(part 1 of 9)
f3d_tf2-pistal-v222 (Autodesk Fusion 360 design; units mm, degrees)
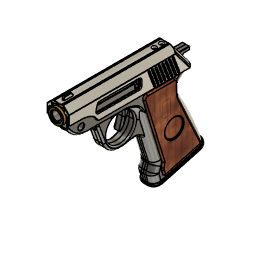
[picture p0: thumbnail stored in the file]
description: Part Number
part number: Dante
part number: catch_housing_front
part number: catch_housing_rear
part number: catch
part number: slide
part number: barrel
part number: priming_handle
part number: front_sight
part number: turnaround
part number: pusher
part number: plunger_tube
part number: plunger_rod
part number: plunger_head
part number: plunger_rod_guide
part number: frame_rear
part number: frame_front
part number: frame
part number: trigger_spring_cover
part number: mag_detent
base_feature "Base Feature1"
base_feature "Base Feature1"
base_feature "Base Feature1"
base_feature "Base Feature1"
base_feature "Base Feature1"
base_feature "Base Feature1"
base_feature "Base Feature1"
base_feature "Base Feature1"
base_feature "Base Feature1"
base_feature "Base Feature1"
base_feature "Base Feature1"
base_feature "Base Feature1"
base_feature "Base Feature1"
base_feature "Base Feature1"
base_feature "Base Feature1"
base_feature "Base Feature1"
base_feature "Base Feature1"
base_feature "Base Feature1"
base_feature "Base Feature1"
base_feature "Base Feature1"
base_feature "Base Feature1"
base_feature "Base Feature1"
base_feature "Base Feature1"
base_feature "Base Feature1"
canvas "Canvas1"
sketch "Sketch1" plane through (-12.5019, 0, 0) normal (-1, 0, 0) x axis (0, -1, 0)
  line L1 (-219.2201, -134.5487) -> (-199.7373, -62.1263)
  line L2 (-219.23, -134.546) -> (-219.2201, -134.5487)
  line L3 (-219.2307, -134.5487) -> (-219.23, -134.546)
  line L4 (-203.3742, -138.8144) -> (-219.2307, -134.5487)
  line L5 (-183.8907, -66.3893) -> (-203.3742, -138.8144)
  line L6 (-199.7373, -62.1263) -> (-183.8907, -66.3893)
  line L7 (-226.3299, -153.1631) -> (-159.8398, -35.3102)
  line L8 (-112.2983, -161.9989) -> (-159.8398, -35.3102)
  line L9 (-112.2983, -161.9989) -> (-132.8986, -57.2662)
  line L10 (-159.8398, -35.3102) -> (-187.1527, -53.6803)
  line L11 (-226.3299, -153.1631) -> (-187.1527, -53.6803)
  circle C1 centre (-159.8398, -35.3102) radius 135.3153
  circle C2 centre (-159.8398, -35.3102) radius 34.7548
  arc A1 centre (-131.4034, -38.3747) radius 28.6011 clockwise from (-130.9894, -66.9728) to (-159.8398, -35.3102)
  arc A2 centre (-188.5512, -53.174) radius 1.4873 clockwise from (-189.9497, -52.6677) to (-187.1527, -53.6803)
  circle C3 centre (-159.8398, -35.3102) radius 14.267
  point P8 (-159.8398, -35.3102)
  point P9 (-159.8398, -35.3102)
  point P10 (-226.3299, -153.1631)
  point P11 (-112.2983, -161.9989)
  point P12 (-159.8398, -35.3102)
  point P13 (-189.9497, -52.6677)
  point P14 (-132.8986, -57.2662)
  point P15 (-130.9894, -66.9728)
  coincident P8 P9
  coincident C1 P10
  coincident C1 P11
  coincident P9 P12
  coincident C2 P13
  coincident C2 P14
  coincident L9 P15
  concentric C1 C3
  dimension "d1" angle L7 L8 = 50
extrude "Extrude1" new body sketch "Sketch1" profile of L4 L5 L6 C1 L7 L8 C2 L9 A1 L10 C3 L11 along normal blind 6.5 and against normal blind 31.5
fillet "Fillet1" radius 13.5
fillet "Fillet2" radius 7.5
shell "Shell1" innerThickness 5
fillet "Fillet3" radius 7
delete_face "DeleteFace1"
fillet "Fillet4" radius 9
sketch "Sketch2" plane through (-19.0019, 0, 0) normal (-1, 0, 0) x axis (0, -1, 0)
  line L1 (-140.4501, -65.5073) -> (-120.8998, -164.9015)
  line L2 (-151.3148, -58.0276) -> (-150.8034, -59.3904)
  line L3 (-187.1527, -53.6803) -> (-171.6782, -43.2725)
  line L4 (-226.3299, -153.1631) -> (-187.1527, -53.6803)
  line L5 (-207.1284, -169.7945) -> (-171.6782, -43.2725)
  line L6 (-171.6782, -43.2725) -> (-177.894, -39.8303)
  arc A1 centre (-131.4034, -38.3747) radius 28.6011 clockwise from (-140.4501, -65.5073) to (-150.8034, -59.3904)
  arc A2 centre (-138.6755, -53.2845) radius 13.5 clockwise from (-151.3148, -58.0276) to (-148.9653, -44.5456)
  arc A3 centre (-159.8398, -35.3102) radius 14.267 clockwise from (-171.6782, -43.2725) to (-148.9653, -44.5456)
  arc A4 centre (-159.8398, -35.3102) radius 135.3153 clockwise from (-120.8998, -164.9015) to (-226.3299, -153.1631)
  point P9 (-171.6782, -43.2725)
  point P13 (-171.6782, -43.2725)
  point P16 (-171.6782, -43.2725)
  coincident P9 P13
  coincident P9 P16
split "Split1"
move "Move1" TranslateX 0 TranslateY 2.5 TranslateZ 10
fillet "Fillet5" radius 20
move_face "MoveFace1" TranslateX 0 TranslateY 0 TranslateZ -10
delete_face "DeleteFace2"
fillet "Fillet6" radius 7.5
delete_face "DeleteFace3"
fillet "Fillet7" radius 17.5
fillet "Fillet8" radius 2
fillet "Fillet9" radius 2
fillet "Fillet10" radius 2
fillet "Fillet11" radius 2
sketch "Sketch1" plane through (0, 0, 0) normal (0, 0, 1) x axis (1, 0, 0)
  circle C1 centre (0, 0) radius 14.3492
  circle C2 centre (0, 0) radius 2.5
extrude "Extrude1" new body sketch "Sketch1" along normal blind 4
sketch "Sketch2" plane through (0, 0, 0) normal (0, 0, 1) x axis (1, 0, 0)
  curve K1 (20.9794, -0.931) -> (16.735, -2.4575)
  curve K2 (20.9794, 0.931) -> (16.735, 2.4575)
  line L1 (16.735, -2.4575) -> (14.1871, -2.0848)
  line L2 (16.735, 2.4575) -> (14.1871, 2.0848)
  line L3 (14.1871, 2.0848) -> (14.1871, -2.0848)
  arc A1 centre (0, 0) radius 21 clockwise from (20.9794, 0.931) to (20.9794, -0.931)
extrude "Extrude2" add sketch "Sketch2" along normal blind 4
fillet "Fillet1" radius 0.8
circular_pattern "C-Pattern1" countU 12 TotalAngle 360
sketch "Sketch3" plane through (0, 0, 0) normal (0, 0, 1) x axis (1, 0, 0)
  circle C1 centre (0, 0) radius 18
sketch "Sketch1" plane through (0, 0, 0) normal (0, 0, 1) x axis (1, 0, 0)
  circle C1 centre (0, 0) radius 16.1492
  circle C2 centre (0, 0) radius 2.5
extrude "Extrude1" new body sketch "Sketch1" along normal blind 4
sketch "Sketch2" plane through (0, 0, 0) normal (0, 0, 1) x axis (1, 0, 0)
  curve K1 (19.4926, -0.5366) -> (16.8599, -1.3577)
  curve K2 (19.4926, 0.5366) -> (16.8599, 1.3577)
  line L1 (16.8599, -1.3577) -> (16.0871, -1.2963)
  line L2 (16.8599, 1.3577) -> (16.0871, 1.2963)
  line L3 (16.0871, 1.2963) -> (16.0871, -1.2963)
  arc A1 centre (0, 0) radius 19.5 clockwise from (19.4926, 0.5366) to (19.4926, -0.5366)
extrude "Extrude2" add sketch "Sketch2" along normal blind 4
fillet "Fillet1" radius 0.8
circular_pattern "C-Pattern1" countU 24 TotalAngle 360
sketch "Sketch3" plane through (0, 0, 0) normal (0, 0, 1) x axis (1, 0, 0)
  circle C1 centre (0, 0) radius 18
sketch "Sketch1" plane through (0, 0, 0) normal (0, 0, 1) x axis (1, 0, 0)
  circle C1 centre (0, 0) radius 17.0492
  circle C2 centre (0, 0) radius 2.5
extrude "Extrude1" new body sketch "Sketch1" along normal blind 4
sketch "Sketch2" plane through (0, 0, 0) normal (0, 0, 1) x axis (1, 0, 0)
  curve K1 (18.7478, -0.2898) -> (16.8953, -0.8053)
  curve K2 (18.7478, 0.2898) -> (16.8953, 0.8053)
  line L1 (16.8953, -0.8053) -> (16.8953, 0.8053)
  arc A1 centre (0, 0) radius 18.75 clockwise from (18.7478, 0.2898) to (18.7478, -0.2898)
extrude "Extrude2" add sketch "Sketch2" along normal blind 4
fillet "Fillet1" radius 0.4
circular_pattern "C-Pattern1" countU 48 TotalAngle 360
sketch "Sketch3" plane through (0, 0, 0) normal (0, 0, 1) x axis (1, 0, 0)
  circle C1 centre (0, 0) radius 18
move "Move1"
position "Position1"
move "Move2"
sketch "Sketch1" plane through (0, 0, 0) normal (0, 0, 1) x axis (1, 0, 0)
  circle C1 centre (0, 0) radius 5.0492
  circle C2 centre (0, 0) radius 2.5
extrude "Extrude1" new body sketch "Sketch1" along normal blind 4
sketch "Sketch2" plane through (0, 0, 0) normal (0, 0, 1) x axis (1, 0, 0)
  curve K1 (6.7454, -0.2496) -> (5.6021, -0.6362)
  curve K2 (6.7454, 0.2496) -> (5.6021, 0.6362)
  line L1 (5.6021, -0.6362) -> (5.007, -0.5697)
  line L2 (5.6021, 0.6362) -> (5.007, 0.5697)
  line L3 (5.007, 0.5697) -> (5.007, -0.5697)
  arc A1 centre (0, 0) radius 6.75 clockwise from (6.7454, 0.2496) to (6.7454, -0.2496)
extrude "Extrude2" add sketch "Sketch2" along normal blind 4
fillet "Fillet1" radius 0.4
circular_pattern "C-Pattern1" countU 16 TotalAngle 360
sketch "Sketch3" plane through (0, 0, 0) normal (0, 0, 1) x axis (1, 0, 0)
  circle C1 centre (0, 0) radius 6
position "Position2"
move "Move1"
move "Move2" RotateAngle 55
move "Move3" TranslateX 0.3 TranslateY 0.5 TranslateZ 0
move "Move4"
sketch "Sketch3" plane through (13.9981, 0, 0) normal (-1, 0, 0) x axis (0, -1, 0)
  line L1 (-155.6873, -48.7302) -> (-149.7495, -64.5534)
  line L2 (-200.2987, -133.9094) -> (-171.9916, -32.8813)
  line L3 (-141.9595, -78.6785) -> (-127.1636, -153.9011)
  line L4 (-144.3334, -73.2936) -> (-142.3421, -78.6001)
  line L5 (-146.405, -67.7731) -> (-144.3334, -73.2936)
  curve K1 (-157.8654, -7.0015) -> (-158.666, -8.2069)
  curve K2 (-157.3054, -7.1515) -> (-157.2147, -8.5958)
  curve K3 (-157.2147, -8.5958) -> (-156.4821, -8.8445)
  curve K4 (-155.531, -7.7539) -> (-156.4821, -8.8445)
  curve K5 (-154.9954, -7.9757) -> (-155.094, -9.4194)
  curve K6 (-155.094, -9.4194) -> (-154.4002, -9.7616)
  curve K7 (-153.3148, -8.8045) -> (-154.4002, -9.7616)
  curve K8 (-152.8128, -9.0943) -> (-153.099, -10.5129)
  curve K9 (-153.099, -10.5129) -> (-152.4557, -10.9427)
  curve K10 (-151.2547, -10.1354) -> (-152.4557, -10.9427)
  curve K11 (-150.7948, -10.4883) -> (-151.2637, -11.8573)
  curve K12 (-151.2637, -11.8573) -> (-150.682, -12.3674)
  curve K13 (-149.3859, -11.7239) -> (-150.682, -12.3674)
  curve K14 (-148.9761, -12.1337) -> (-149.6196, -13.4298)
  curve K15 (-149.6196, -13.4298) -> (-149.1095, -14.0115)
  curve K16 (-147.7405, -13.5426) -> (-149.1095, -14.0115)
  curve K17 (-147.3876, -14.0025) -> (-148.1949, -15.2035)
  curve K18 (-148.1949, -15.2035) -> (-147.7651, -15.8468)
  curve K19 (-146.3466, -15.5606) -> (-147.7651, -15.8468)
  curve K20 (-146.0567, -16.0626) -> (-147.0138, -17.148)
  curve K21 (-147.0138, -17.148) -> (-146.6716, -17.8418)
  curve K22 (-145.2279, -17.7432) -> (-146.6716, -17.8418)
  curve K23 (-145.0061, -18.2788) -> (-146.0967, -19.2299)
  curve K24 (-146.0967, -19.2299) -> (-145.848, -19.9625)
  curve K25 (-144.4037, -20.0532) -> (-145.848, -19.9625)
  curve K26 (-144.2537, -20.6131) -> (-145.4591, -21.4138)
  curve K27 (-145.4591, -21.4138) -> (-145.3082, -22.1726)
  curve K28 (-143.8881, -22.451) -> (-145.3082, -22.1726)
  curve K29 (-143.8125, -23.0257) -> (-145.1121, -23.6622)
  curve K30 (-145.1121, -23.6622) -> (-145.0615, -24.4342)
  curve K31 (-143.6899, -24.8956) -> (-145.0615, -24.4342)
  curve K32 (-143.6899, -25.4753) -> (-145.0615, -25.9367)
  curve K33 (-145.0615, -25.9367) -> (-145.1121, -26.7087)
  curve K34 (-143.8125, -27.3452) -> (-145.1121, -26.7087)
  curve K35 (-143.8881, -27.9199) -> (-145.3082, -28.1983)
  curve K36 (-145.3082, -28.1983) -> (-145.4591, -28.9571)
  curve K37 (-144.2537, -29.7578) -> (-145.4591, -28.9571)
  curve K38 (-144.4037, -30.3177) -> (-145.848, -30.4084)
  curve K39 (-145.848, -30.4084) -> (-146.0967, -31.141)
  curve K40 (-145.0061, -32.0922) -> (-146.0967, -31.141)
  curve K41 (-145.2279, -32.6277) -> (-146.6716, -32.5291)
  curve K42 (-146.6716, -32.5291) -> (-147.0138, -33.223)
  curve K43 (-146.0567, -34.3083) -> (-147.0138, -33.223)
  curve K44 (-146.3466, -34.8104) -> (-147.7651, -34.5242)
  curve K45 (-147.7651, -34.5242) -> (-148.1949, -35.1674)
  curve K46 (-147.3876, -36.3684) -> (-148.1949, -35.1674)
  curve K47 (-147.7405, -36.8283) -> (-149.1095, -36.3594)
  curve K48 (-149.1095, -36.3594) -> (-149.6196, -36.9411)
  curve K49 (-148.9761, -38.2372) -> (-149.6196, -36.9411)
  curve K50 (-149.3859, -38.6471) -> (-150.682, -38.0035)
  curve K51 (-150.682, -38.0035) -> (-151.2637, -38.5136)
  curve K52 (-150.7948, -39.8826) -> (-151.2637, -38.5136)
  curve K53 (-151.2547, -40.2355) -> (-152.4557, -39.4283)
  curve K54 (-152.4557, -39.4283) -> (-153.099, -39.8581)
  curve K55 (-152.8128, -41.2766) -> (-153.099, -39.8581)
  curve K56 (-153.3148, -41.5664) -> (-154.4002, -40.6093)
  curve K57 (-154.4002, -40.6093) -> (-155.094, -40.9515)
  curve K58 (-154.9954, -42.3952) -> (-155.094, -40.9515)
  curve K59 (-155.531, -42.6171) -> (-156.4821, -41.5265)
  curve K60 (-156.4821, -41.5265) -> (-157.2147, -41.7752)
  curve K61 (-157.3054, -43.2194) -> (-157.2147, -41.7752)
  curve K62 (-157.8654, -43.3694) -> (-158.666, -42.164)
  curve K63 (-158.666, -42.164) -> (-159.4248, -42.315)
  curve K64 (-159.7032, -43.735) -> (-159.4248, -42.315)
  curve K65 (-160.278, -43.8107) -> (-160.9144, -42.5111)
  curve K66 (-160.9144, -42.5111) -> (-161.6864, -42.5617)
  curve K67 (-162.1478, -43.9332) -> (-161.6864, -42.5617)
  curve K68 (-162.7275, -43.9332) -> (-163.1889, -42.5617)
  curve K69 (-163.1889, -42.5617) -> (-163.9609, -42.5111)
  curve K70 (-164.5974, -43.8107) -> (-163.9609, -42.5111)
  curve K71 (-165.1721, -43.735) -> (-165.4505, -42.315)
  curve K72 (-165.4505, -42.315) -> (-166.2093, -42.164)
  curve K73 (-167.01, -43.3694) -> (-166.2093, -42.164)
  curve K74 (-167.5699, -43.2194) -> (-167.6606, -41.7752)
  curve K75 (-167.6606, -41.7752) -> (-168.3932, -41.5265)
  curve K76 (-169.3444, -42.6171) -> (-168.3932, -41.5265)
  curve K77 (-169.8799, -42.3952) -> (-169.7813, -40.9515)
  curve K78 (-169.7813, -40.9515) -> (-170.4752, -40.6093)
  curve K79 (-171.5605, -41.5664) -> (-170.4752, -40.6093)
  curve K80 (-172.0626, -41.2766) -> (-171.7764, -39.8581)
  curve K81 (-171.7764, -39.8581) -> (-172.4196, -39.4283)
  curve K82 (-173.6206, -40.2355) -> (-172.4196, -39.4283)
  curve K83 (-174.0805, -39.8826) -> (-173.6116, -38.5136)
  curve K84 (-173.6116, -38.5136) -> (-174.1933, -38.0035)
  curve K85 (-175.4894, -38.6471) -> (-174.1933, -38.0035)
  curve K86 (-175.8993, -38.2372) -> (-175.2557, -36.9411)
  curve K87 (-175.2557, -36.9411) -> (-175.7658, -36.3594)
  curve K88 (-177.1348, -36.8283) -> (-175.7658, -36.3594)
  curve K89 (-177.4877, -36.3684) -> (-176.6805, -35.1674)
  curve K90 (-176.6805, -35.1674) -> (-177.1103, -34.5242)
  curve K91 (-178.5288, -34.8104) -> (-177.1103, -34.5242)
  curve K92 (-178.8186, -34.3083) -> (-177.8615, -33.223)
  curve K93 (-177.8615, -33.223) -> (-178.2037, -32.5291)
  curve K94 (-179.6474, -32.6277) -> (-178.2037, -32.5291)
  curve K95 (-179.8693, -32.0922) -> (-178.7787, -31.141)
  curve K96 (-178.7787, -31.141) -> (-179.0274, -30.4084)
  curve K97 (-180.4716, -30.3177) -> (-179.0274, -30.4084)
  curve K98 (-180.6216, -29.7578) -> (-179.4162, -28.9571)
  curve K99 (-179.4162, -28.9571) -> (-179.5672, -28.1983)
  curve K100 (-180.9872, -27.9199) -> (-179.5672, -28.1983)
  curve K101 (-181.0629, -27.3452) -> (-179.7633, -26.7087)
  curve K102 (-179.7633, -26.7087) -> (-179.8139, -25.9367)
  curve K103 (-181.1854, -25.4753) -> (-179.8139, -25.9367)
  curve K104 (-181.1854, -24.8956) -> (-179.8139, -24.4342)
  curve K105 (-179.8139, -24.4342) -> (-179.7633, -23.6622)
  curve K106 (-181.0629, -23.0257) -> (-179.7633, -23.6622)
  curve K107 (-180.9872, -22.451) -> (-179.5672, -22.1726)
  curve K108 (-179.5672, -22.1726) -> (-179.4162, -21.4138)
  curve K109 (-180.6216, -20.6131) -> (-179.4162, -21.4138)
  curve K110 (-180.4716, -20.0532) -> (-179.0274, -19.9625)
  curve K111 (-179.0274, -19.9625) -> (-178.7787, -19.2299)
  curve K112 (-179.8693, -18.2788) -> (-178.7787, -19.2299)
  curve K113 (-179.6474, -17.7432) -> (-178.2037, -17.8418)
  curve K114 (-178.2037, -17.8418) -> (-177.8615, -17.148)
  curve K115 (-178.8186, -16.0626) -> (-177.8615, -17.148)
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extrude "Extrude2" new body sketch "Sketch3" against normal blind 5
move_face "MoveFace2"
sketch "Sketch4" plane through (17.9981, 0, 0) normal (1, 0, 0) x axis (0, 1, 0)
  curve K1 (156.4821, -8.8445) -> (157.2147, -8.5958)
  curve K2 (155.531, -7.7539) -> (156.4821, -8.8445)
  curve K3 (155.094, -9.4194) -> (154.9954, -7.9757)
  curve K4 (154.4002, -9.7616) -> (155.094, -9.4194)
  curve K5 (153.3148, -8.8045) -> (154.4002, -9.7616)
  curve K6 (153.099, -10.5129) -> (152.8128, -9.0943)
  curve K7 (152.4557, -10.9427) -> (153.099, -10.5129)
  curve K8 (151.2547, -10.1354) -> (152.4557, -10.9427)
  curve K9 (151.2637, -11.8573) -> (150.7948, -10.4883)
  curve K10 (150.682, -12.3674) -> (151.2637, -11.8573)
  curve K11 (149.3859, -11.7239) -> (150.682, -12.3674)
  curve K12 (149.6196, -13.4298) -> (148.9761, -12.1337)
  curve K13 (149.1095, -14.0115) -> (149.6196, -13.4298)
  curve K14 (147.7405, -13.5426) -> (149.1095, -14.0115)
  curve K15 (148.1949, -15.2035) -> (147.3876, -14.0025)
  curve K16 (147.7651, -15.8468) -> (148.1949, -15.2035)
  curve K17 (146.3466, -15.5606) -> (147.7651, -15.8468)
  curve K18 (147.0138, -17.148) -> (146.0567, -16.0626)
  curve K19 (146.6716, -17.8418) -> (147.0138, -17.148)
  curve K20 (145.2279, -17.7432) -> (146.6716, -17.8418)
  curve K21 (146.0967, -19.2299) -> (145.0061, -18.2788)
  curve K22 (145.848, -19.9625) -> (146.0967, -19.2299)
  curve K23 (144.4037, -20.0532) -> (145.848, -19.9625)
  curve K24 (145.4591, -21.4138) -> (144.2537, -20.6131)
  curve K25 (145.3082, -22.1726) -> (145.4591, -21.4138)
  curve K26 (143.8881, -22.451) -> (145.3082, -22.1726)
  curve K27 (145.1121, -23.6622) -> (143.8125, -23.0257)
  curve K28 (145.0615, -24.4342) -> (145.1121, -23.6622)
  curve K29 (143.6899, -24.8956) -> (145.0615, -24.4342)
  curve K30 (145.0615, -25.9367) -> (143.6899, -25.4753)
  curve K31 (145.1121, -26.7087) -> (145.0615, -25.9367)
  curve K32 (143.8125, -27.3452) -> (145.1121, -26.7087)
  curve K33 (145.3082, -28.1983) -> (143.8881, -27.9199)
  curve K34 (145.4591, -28.9571) -> (145.3082, -28.1983)
  curve K35 (144.2537, -29.7578) -> (145.4591, -28.9571)
  curve K36 (145.848, -30.4084) -> (144.4037, -30.3177)
  curve K37 (146.0967, -31.141) -> (145.848, -30.4084)
  curve K38 (145.0061, -32.0922) -> (146.0967, -31.141)
  curve K39 (146.6716, -32.5291) -> (145.2279, -32.6277)
  curve K40 (147.0138, -33.223) -> (146.6716, -32.5291)
  curve K41 (146.0567, -34.3083) -> (147.0138, -33.223)
  curve K42 (147.7651, -34.5242) -> (146.3466, -34.8104)
  curve K43 (148.1949, -35.1674) -> (147.7651, -34.5242)
  curve K44 (147.3876, -36.3684) -> (148.1949, -35.1674)
  curve K45 (149.1095, -36.3594) -> (147.7405, -36.8283)
  curve K46 (149.6196, -36.9411) -> (149.1095, -36.3594)
  curve K47 (148.9761, -38.2372) -> (149.6196, -36.9411)
  curve K48 (150.682, -38.0035) -> (149.3859, -38.6471)
  curve K49 (151.2637, -38.5136) -> (150.682, -38.0035)
  curve K50 (150.7948, -39.8826) -> (151.2637, -38.5136)
  curve K51 (152.4557, -39.4283) -> (151.2547, -40.2355)
  curve K52 (153.099, -39.8581) -> (152.4557, -39.4283)
  curve K53 (152.8128, -41.2766) -> (153.099, -39.8581)
  curve K54 (154.4002, -40.6093) -> (153.3148, -41.5664)
  curve K55 (155.094, -40.9515) -> (154.4002, -40.6093)
  curve K56 (154.9954, -42.3952) -> (155.094, -40.9515)
  curve K57 (156.4821, -41.5265) -> (155.531, -42.6171)
  curve K58 (156.5648, -41.4357) -> (156.4821, -41.5265)
  line L1 (173.9763, -39.9646) -> (171.9916, -32.8813)
  curve K59 (173.6116, -38.5136) -> (174.0805, -39.8826)
  curve K60 (174.1933, -38.0035) -> (173.6116, -38.5136)
  curve K61 (175.4894, -38.6471) -> (174.1933, -38.0035)
  curve K62 (175.2557, -36.9411) -> (175.8993, -38.2372)
  curve K63 (175.7658, -36.3594) -> (175.2557, -36.9411)
  curve K64 (177.1348, -36.8283) -> (175.7658, -36.3594)
  curve K65 (176.6805, -35.1674) -> (177.4877, -36.3684)
  curve K66 (177.1103, -34.5242) -> (176.6805, -35.1674)
  curve K67 (178.5288, -34.8104) -> (177.1103, -34.5242)
  curve K68 (177.8615, -33.223) -> (178.8186, -34.3083)
  curve K69 (178.2037, -32.5291) -> (177.8615, -33.223)
  curve K70 (179.6474, -32.6277) -> (178.2037, -32.5291)
  curve K71 (178.7787, -31.141) -> (179.8693, -32.0922)
  curve K72 (179.0274, -30.4084) -> (178.7787, -31.141)
  curve K73 (180.4716, -30.3177) -> (179.0274, -30.4084)
  curve K74 (179.4162, -28.9571) -> (180.6216, -29.7578)
  curve K75 (179.5672, -28.1983) -> (179.4162, -28.9571)
  curve K76 (180.9872, -27.9199) -> (179.5672, -28.1983)
  curve K77 (179.7633, -26.7087) -> (181.0629, -27.3452)
  curve K78 (179.8139, -25.9367) -> (179.7633, -26.7087)
  curve K79 (181.1854, -25.4753) -> (179.8139, -25.9367)
  curve K80 (179.8139, -24.4342) -> (181.1854, -24.8956)
  curve K81 (179.7633, -23.6622) -> (179.8139, -24.4342)
  curve K82 (181.0629, -23.0257) -> (179.7633, -23.6622)
  curve K83 (179.5672, -22.1726) -> (180.9872, -22.451)
  curve K84 (179.4162, -21.4138) -> (179.5672, -22.1726)
  curve K85 (180.6216, -20.6131) -> (179.4162, -21.4138)
  curve K86 (179.0274, -19.9625) -> (180.4716, -20.0532)
  curve K87 (178.7787, -19.2299) -> (179.0274, -19.9625)
  curve K88 (179.8693, -18.2788) -> (178.7787, -19.2299)
  curve K89 (178.2037, -17.8418) -> (179.6474, -17.7432)
  curve K90 (177.8615, -17.148) -> (178.2037, -17.8418)
  curve K91 (178.8186, -16.0626) -> (177.8615, -17.148)
  curve K92 (177.1103, -15.8468) -> (178.5288, -15.5606)
  curve K93 (176.6805, -15.2035) -> (177.1103, -15.8468)
  curve K94 (177.4877, -14.0025) -> (176.6805, -15.2035)
  curve K95 (175.7658, -14.0115) -> (177.1348, -13.5426)
  curve K96 (175.2557, -13.4298) -> (175.7658, -14.0115)
  curve K97 (175.8993, -12.1337) -> (175.2557, -13.4298)
  curve K98 (174.1933, -12.3674) -> (175.4894, -11.7239)
  curve K99 (173.6116, -11.8573) -> (174.1933, -12.3674)
  curve K100 (174.0805, -10.4883) -> (173.6116, -11.8573)
  curve K101 (172.4196, -10.9427) -> (173.6206, -10.1354)
  curve K102 (171.7764, -10.5129) -> (172.4196, -10.9427)
  curve K103 (172.0626, -9.0943) -> (171.7764, -10.5129)
  curve K104 (170.4752, -9.7616) -> (171.5605, -8.8045)
  curve K105 (169.7813, -9.4194) -> (170.4752, -9.7616)
  curve K106 (169.8799, -7.9757) -> (169.7813, -9.4194)
  curve K107 (168.3932, -8.8445) -> (169.3444, -7.7539)
  curve K108 (167.6606, -8.5958) -> (168.3932, -8.8445)
  curve K109 (167.5699, -7.1515) -> (167.6606, -8.5958)
  curve K110 (166.2093, -8.2069) -> (167.01, -7.0015)
  curve K111 (165.4505, -8.056) -> (166.2093, -8.2069)
  curve K112 (165.1721, -6.6359) -> (165.4505, -8.056)
  curve K113 (163.9609, -7.8599) -> (164.5974, -6.5603)
  curve K114 (163.1889, -7.8093) -> (163.9609, -7.8599)
  curve K115 (162.7275, -6.4377) -> (163.1889, -7.8093)
  curve K116 (161.6864, -7.8093) -> (162.1478, -6.4377)
  curve K117 (160.9144, -7.8599) -> (161.6864, -7.8093)
  curve K118 (160.278, -6.5603) -> (160.9144, -7.8599)
  curve K119 (159.4248, -8.056) -> (159.7032, -6.6359)
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  point P84 (162.3398, -25.3102)
  point P171 (162.3398, -25.3102)
  point P173 (162.3398, -25.3102)
  coincident P84 P171
  coincident P84 P173
split "Split2"
mirror "Mirror1" mirrorStitchTolerance 0.1
combine "Combine1"
move "Move4" TranslateX -3 TranslateY 0 TranslateZ 0
move "Move5"
position "Position3"
sketch "Sketch5" plane through (13.9981, 0, 0) normal (1, 0, 0) x axis (0, 1, 0)
  curve K1 (180.9983, -0.0283) -> (181.799, -1.2337)
  curve K2 (180.4384, -0.1784) -> (180.3477, -1.6226)
  curve K3 (180.3477, -1.6226) -> (179.6151, -1.8713)
  curve K4 (178.664, -0.7807) -> (179.6151, -1.8713)
  curve K5 (178.1284, -1.0025) -> (178.227, -2.4463)
  curve K6 (178.227, -2.4463) -> (177.5331, -2.7884)
  curve K7 (176.4478, -1.8313) -> (177.5331, -2.7884)
  curve K8 (175.9458, -2.1212) -> (176.2319, -3.5397)
  curve K9 (176.2319, -3.5397) -> (175.5887, -3.9695)
  curve K10 (174.3877, -3.1622) -> (175.5887, -3.9695)
  curve K11 (173.9278, -3.5151) -> (174.3967, -4.8841)
  curve K12 (174.3967, -4.8841) -> (173.815, -5.3942)
  curve K13 (172.5189, -4.7507) -> (173.815, -5.3942)
  curve K14 (172.109, -5.1606) -> (172.7526, -6.4567)
  curve K15 (172.7526, -6.4567) -> (172.2425, -7.0383)
  curve K16 (170.8735, -6.5694) -> (172.2425, -7.0383)
  curve K17 (170.5206, -7.0293) -> (171.3278, -8.2303)
  curve K18 (171.3278, -8.2303) -> (170.898, -8.8736)
  curve K19 (169.4795, -8.5874) -> (170.898, -8.8736)
  curve K20 (169.1897, -9.0894) -> (170.1468, -10.1748)
  curve K21 (170.1468, -10.1748) -> (169.8046, -10.8686)
  curve K22 (168.3609, -10.7701) -> (169.8046, -10.8686)
  curve K23 (168.139, -11.3056) -> (169.2296, -12.2568)
  curve K24 (169.2296, -12.2568) -> (168.9809, -12.9893)
  curve K25 (167.5367, -13.08) -> (168.9809, -12.9893)
  curve K26 (167.3867, -13.64) -> (168.5921, -14.4406)
  curve K27 (168.5921, -14.4406) -> (168.4411, -15.1994)
  curve K28 (167.0211, -15.4779) -> (168.4411, -15.1994)
  curve K29 (166.9454, -16.0526) -> (168.245, -16.6891)
  curve K30 (168.245, -16.6891) -> (168.1944, -17.461)
  curve K31 (166.8229, -17.9225) -> (168.1944, -17.461)
  curve K32 (166.8229, -18.5021) -> (168.1944, -18.9635)
  curve K33 (168.1944, -18.9635) -> (168.245, -19.7355)
  curve K34 (166.9454, -20.372) -> (168.245, -19.7355)
  curve K35 (167.0211, -20.9467) -> (168.4411, -21.2252)
  curve K36 (168.4411, -21.2252) -> (168.5921, -21.9839)
  curve K37 (167.3867, -22.7846) -> (168.5921, -21.9839)
  curve K38 (167.5367, -23.3445) -> (168.9809, -23.4352)
  curve K39 (168.9809, -23.4352) -> (169.2296, -24.1678)
  curve K40 (168.139, -25.119) -> (169.2296, -24.1678)
  curve K41 (168.3609, -25.6545) -> (169.8046, -25.5559)
  curve K42 (169.8046, -25.5559) -> (170.1468, -26.2498)
  curve K43 (169.1897, -27.3352) -> (170.1468, -26.2498)
  curve K44 (169.4795, -27.8372) -> (170.898, -27.551)
  curve K45 (170.898, -27.551) -> (171.3278, -28.1942)
  curve K46 (170.5206, -29.3953) -> (171.3278, -28.1942)
  curve K47 (170.8735, -29.8551) -> (172.2425, -29.3863)
  curve K48 (172.2425, -29.3863) -> (172.7526, -29.9679)
  curve K49 (172.109, -31.264) -> (172.7526, -29.9679)
  curve K50 (172.5189, -31.6739) -> (173.815, -31.0303)
  curve K51 (173.815, -31.0303) -> (174.3967, -31.5404)
  curve K52 (173.9278, -32.9094) -> (174.3967, -31.5404)
  curve K53 (174.3877, -33.2623) -> (175.5887, -32.4551)
  curve K54 (175.5887, -32.4551) -> (176.2319, -32.8849)
  curve K55 (175.9458, -34.3034) -> (176.2319, -32.8849)
  curve K56 (176.4478, -34.5932) -> (177.5331, -33.6361)
  curve K57 (177.5331, -33.6361) -> (178.227, -33.9783)
  curve K58 (178.1284, -35.422) -> (178.227, -33.9783)
  curve K59 (178.664, -35.6439) -> (179.6151, -34.5533)
  curve K60 (179.6151, -34.5533) -> (180.3477, -34.802)
  curve K61 (180.4384, -36.2462) -> (180.3477, -34.802)
  curve K62 (180.9983, -36.3962) -> (181.799, -35.1908)
  curve K63 (181.799, -35.1908) -> (182.5578, -35.3418)
  curve K64 (182.8362, -36.7618) -> (182.5578, -35.3418)
  curve K65 (183.4109, -36.8375) -> (184.0474, -35.5379)
  curve K66 (184.0474, -35.5379) -> (184.8194, -35.5885)
  curve K67 (185.2808, -36.96) -> (184.8194, -35.5885)
  curve K68 (185.8605, -36.96) -> (186.3219, -35.5885)
  curve K69 (186.3219, -35.5885) -> (187.0939, -35.5379)
  curve K70 (187.7304, -36.8375) -> (187.0939, -35.5379)
  curve K71 (188.3051, -36.7618) -> (188.5835, -35.3418)
  curve K72 (188.5835, -35.3418) -> (189.3423, -35.1908)
  curve K73 (190.143, -36.3962) -> (189.3423, -35.1908)
  curve K74 (190.7029, -36.2462) -> (190.7936, -34.802)
  curve K75 (190.7936, -34.802) -> (191.5262, -34.5533)
  curve K76 (192.4773, -35.6439) -> (191.5262, -34.5533)
  curve K77 (193.0129, -35.422) -> (192.9143, -33.9783)
  curve K78 (192.9143, -33.9783) -> (193.6081, -33.6361)
  curve K79 (194.6935, -34.5932) -> (193.6081, -33.6361)
  curve K80 (195.1955, -34.3034) -> (194.9093, -32.8849)
  curve K81 (194.9093, -32.8849) -> (195.5526, -32.4551)
  curve K82 (196.7536, -33.2623) -> (195.5526, -32.4551)
  curve K83 (197.2135, -32.9094) -> (196.7446, -31.5404)
  curve K84 (196.7446, -31.5404) -> (197.3263, -31.0303)
  curve K85 (198.6224, -31.6739) -> (197.3263, -31.0303)
  curve K86 (199.0322, -31.264) -> (198.3887, -29.9679)
  curve K87 (198.3887, -29.9679) -> (198.8988, -29.3863)
  curve K88 (200.2678, -29.8551) -> (198.8988, -29.3863)
  curve K89 (200.6207, -29.3953) -> (199.8134, -28.1942)
  curve K90 (199.8134, -28.1942) -> (200.2432, -27.551)
  curve K91 (201.6618, -27.8372) -> (200.2432, -27.551)
  curve K92 (201.9516, -27.3352) -> (200.9945, -26.2498)
  curve K93 (200.9945, -26.2498) -> (201.3367, -25.5559)
  curve K94 (202.7804, -25.6545) -> (201.3367, -25.5559)
  curve K95 (203.0022, -25.119) -> (201.9116, -24.1678)
  curve K96 (201.9116, -24.1678) -> (202.1603, -23.4352)
  curve K97 (203.6046, -23.3445) -> (202.1603, -23.4352)
  curve K98 (203.7546, -22.7846) -> (202.5492, -21.9839)
  curve K99 (202.5492, -21.9839) -> (202.7001, -21.2252)
  curve K100 (204.1202, -20.9467) -> (202.7001, -21.2252)
  curve K101 (204.1958, -20.372) -> (202.8962, -19.7355)
  curve K102 (202.8962, -19.7355) -> (202.9468, -18.9635)
  curve K103 (204.3184, -18.5021) -> (202.9468, -18.9635)
  curve K104 (204.3184, -17.9225) -> (202.9468, -17.461)
  curve K105 (202.9468, -17.461) -> (202.8962, -16.6891)
  curve K106 (204.1958, -16.0526) -> (202.8962, -16.6891)
  curve K107 (204.1202, -15.4779) -> (202.7001, -15.1994)
  curve K108 (202.7001, -15.1994) -> (202.5492, -14.4406)
  curve K109 (203.7546, -13.64) -> (202.5492, -14.4406)
  curve K110 (203.6046, -13.08) -> (202.1603, -12.9893)
  curve K111 (202.1603, -12.9893) -> (201.9116, -12.2568)
  curve K112 (203.0022, -11.3056) -> (201.9116, -12.2568)
  curve K113 (202.7804, -10.7701) -> (201.3367, -10.8686)
  curve K114 (201.3367, -10.8686) -> (200.9945, -10.1748)
  curve K115 (201.9516, -9.0894) -> (200.9945, -10.1748)
  curve K116 (201.6618, -8.5874) -> (200.2432, -8.8736)
  curve K117 (200.2432, -8.8736) -> (199.8134, -8.2303)
  curve K118 (200.6207, -7.0293) -> (199.8134, -8.2303)
  curve K119 (200.2678, -6.5694) -> (198.8988, -7.0383)
  curve K120 (198.8988, -7.0383) -> (198.3887, -6.4567)
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sketch "Sketch1" plane through (0, 0, 0) normal (0, 0, 1) x axis (1, 0, 0)
  circle C1 centre (0, 0) radius 32.3492
  circle C2 centre (0, 0) radius 0.5
extrude "Extrude1" new body sketch "Sketch1" along normal blind 2
sketch "Sketch2" plane through (0, 0, 0) normal (0, 0, 1) x axis (1, 0, 0)
  curve K1 (38.9852, -1.0732) -> (33.7198, -2.7154)
  curve K2 (38.9852, 1.0732) -> (33.7198, 2.7154)
  line L1 (33.7198, -2.7154) -> (32.2349, -2.5966)
  line L2 (33.7198, 2.7154) -> (32.2349, 2.5966)
  line L3 (32.2349, 2.5966) -> (32.2349, -2.5966)
  arc A1 centre (0, 0) radius 39 clockwise from (38.9852, 1.0732) to (38.9852, -1.0732)
extrude "Extrude2" add sketch "Sketch2" along normal blind 2
fillet "Fillet1" radius 1
circular_pattern "C-Pattern1" countU 24 TotalAngle 360
sketch "Sketch3" plane through (0, 0, 0) normal (0, 0, 1) x axis (1, 0, 0)
  circle C1 centre (0, 0) radius 36
position "Position4"
sketch "Sketch6" plane through (13.9981, 0, 0) normal (1, 0, 0) x axis (0, 1, 0)
  line L1 (177.2846, -52.7198) -> (177.3241, -52.2261)
  curve K1 (178.9268, -57.9852) -> (177.2846, -52.7198)
  curve K2 (182.7154, -52.7198) -> (181.0732, -57.9852)
  line L2 (182.6759, -52.2261) -> (182.7154, -52.7198)
  line L3 (186.1045, -52.2736) -> (186.0148, -51.7865)
  curve K3 (189.0535, -56.9346) -> (186.1045, -52.2736)
  curve K4 (191.3502, -50.868) -> (191.1267, -56.3791)
  line L4 (191.1842, -50.4014) -> (191.3502, -50.868)
  line L5 (194.5083, -49.5599) -> (194.2957, -49.1126)
  curve K5 (198.5632, -53.2988) -> (194.5083, -49.5599)
  curve K6 (199.2115, -46.8445) -> (200.422, -52.2256)
  line L6 (198.9304, -46.4367) -> (199.2115, -46.8445)
  line L7 (201.9234, -44.7635) -> (201.6023, -44.3865)
  curve K7 (206.8079, -47.3256) -> (201.9234, -44.7635)
  curve K8 (205.7635, -40.9234) -> (208.3256, -45.8079)
  line L8 (205.3865, -40.6023) -> (205.7635, -40.9234)
  line L9 (207.8445, -38.2115) -> (207.4367, -37.9304)
  curve K9 (213.2256, -39.422) -> (207.8445, -38.2115)
  curve K10 (210.5599, -33.5083) -> (214.2988, -37.5632)
  line L10 (210.1126, -33.2957) -> (210.5599, -33.5083)
  line L11 (211.868, -30.3502) -> (211.4014, -30.1842)
  curve K11 (217.3791, -30.1267) -> (211.868, -30.3502)
  curve K12 (213.2736, -25.1045) -> (217.9346, -28.0535)
  line L12 (212.7865, -25.0148) -> (213.2736, -25.1045)
  line L13 (213.7198, -21.7154) -> (213.2261, -21.6759)
  curve K13 (218.9852, -20.0732) -> (213.7198, -21.7154)
  curve K14 (213.7198, -16.2846) -> (218.9852, -17.9268)
  line L14 (213.2261, -16.3241) -> (213.7198, -16.2846)
  line L15 (213.2736, -12.8955) -> (212.7865, -12.9852)
  curve K15 (217.9346, -9.9465) -> (213.2736, -12.8955)
  curve K16 (211.868, -7.6498) -> (217.3791, -7.8733)
  line L16 (211.4014, -7.8158) -> (211.868, -7.6498)
  line L17 (210.5599, -4.4917) -> (210.1126, -4.7043)
  curve K17 (214.2988, -0.4368) -> (210.5599, -4.4917)
  curve K18 (207.8445, 0.2115) -> (213.2256, 1.422)
  line L18 (207.4367, -0.0696) -> (207.8445, 0.2115)
  line L19 (205.7635, 2.9234) -> (205.3865, 2.6023)
  curve K19 (208.3256, 7.8079) -> (205.7635, 2.9234)
  curve K20 (201.9234, 6.7635) -> (206.8079, 9.3256)
  line L20 (201.6023, 6.3865) -> (201.9234, 6.7635)
  line L21 (199.2115, 8.8445) -> (198.9304, 8.4367)
  curve K21 (200.422, 14.2256) -> (199.2115, 8.8445)
  curve K22 (194.5083, 11.5599) -> (198.5632, 15.2988)
  line L22 (194.2957, 11.1126) -> (194.5083, 11.5599)
  line L23 (191.3502, 12.868) -> (191.1842, 12.4014)
  curve K23 (191.1267, 18.3791) -> (191.3502, 12.868)
  curve K24 (186.1045, 14.2736) -> (189.0535, 18.9346)
  line L24 (186.0148, 13.7865) -> (186.1045, 14.2736)
  line L25 (182.7154, 14.7198) -> (182.6759, 14.2261)
  curve K25 (181.0732, 19.9852) -> (182.7154, 14.7198)
  curve K26 (177.2846, 14.7198) -> (178.9268, 19.9852)
  line L26 (177.3241, 14.2261) -> (177.2846, 14.7198)
  line L27 (173.8955, 14.2736) -> (173.9852, 13.7865)
  curve K27 (170.9465, 18.9346) -> (173.8955, 14.2736)
  curve K28 (168.6498, 12.868) -> (168.8733, 18.3791)
  line L28 (168.8158, 12.4014) -> (168.6498, 12.868)
  line L29 (165.4917, 11.5599) -> (165.7043, 11.1126)
  curve K29 (161.4368, 15.2988) -> (165.4917, 11.5599)
  curve K30 (160.7885, 8.8445) -> (159.578, 14.2256)
  line L30 (161.0696, 8.4367) -> (160.7885, 8.8445)
  line L31 (158.0766, 6.7635) -> (158.3977, 6.3865)
  curve K31 (153.1921, 9.3256) -> (158.0766, 6.7635)
  curve K32 (154.2365, 2.9234) -> (151.6744, 7.8079)
  line L32 (154.6135, 2.6023) -> (154.2365, 2.9234)
  line L33 (152.1555, 0.2115) -> (152.5633, -0.0696)
  curve K33 (146.7744, 1.422) -> (152.1555, 0.2115)
  curve K34 (149.4401, -4.4917) -> (145.7012, -0.4368)
  line L34 (149.8874, -4.7043) -> (149.4401, -4.4917)
  line L35 (148.132, -7.6498) -> (148.5986, -7.8158)
  curve K35 (142.6209, -7.8733) -> (148.132, -7.6498)
  curve K36 (146.7264, -12.8955) -> (142.0654, -9.9465)
  line L36 (147.2135, -12.9852) -> (146.7264, -12.8955)
  line L37 (146.2802, -16.2846) -> (146.7739, -16.3241)
  curve K37 (141.0148, -17.9268) -> (146.2802, -16.2846)
  curve K38 (146.2802, -21.7154) -> (141.0148, -20.0732)
  line L38 (146.7739, -21.6759) -> (146.2802, -21.7154)
  line L39 (146.7264, -25.1045) -> (147.2135, -25.0148)
  curve K39 (142.0654, -28.0535) -> (146.7264, -25.1045)
  curve K40 (148.132, -30.3502) -> (142.6209, -30.1267)
  line L40 (148.5986, -30.1842) -> (148.132, -30.3502)
  line L41 (149.4401, -33.5083) -> (149.8874, -33.2957)
  curve K41 (145.7012, -37.5632) -> (149.4401, -33.5083)
  curve K42 (152.1555, -38.2115) -> (146.7744, -39.422)
  line L42 (152.5633, -37.9304) -> (152.1555, -38.2115)
  line L43 (154.2365, -40.9234) -> (154.6135, -40.6023)
  curve K43 (151.6744, -45.8079) -> (154.2365, -40.9234)
  curve K44 (158.0766, -44.7635) -> (153.1921, -47.3256)
  line L44 (158.3977, -44.3865) -> (158.0766, -44.7635)
  line L45 (160.7885, -46.8445) -> (161.0696, -46.4367)
  curve K45 (159.578, -52.2256) -> (160.7885, -46.8445)
  curve K46 (165.4917, -49.5599) -> (161.4368, -53.2988)
  line L46 (165.7043, -49.1126) -> (165.4917, -49.5599)
  line L47 (168.6498, -50.868) -> (168.8158, -50.4014)
  curve K47 (168.8733, -56.3791) -> (168.6498, -50.868)
  curve K48 (173.8955, -52.2736) -> (170.9465, -56.9346)
  line L48 (173.9852, -51.7865) -> (173.8955, -52.2736)
  arc A1 centre (180, -19) radius 32.3492 clockwise from (176.4374, -51.1524) to (175.1195, -50.9789)
  arc A2 centre (176.3273, -52.1463) radius 1 clockwise from (176.4374, -51.1524) to (177.3241, -52.2261)
  arc A3 centre (180, -19) radius 39 clockwise from (181.0732, -57.9852) to (178.9268, -57.9852)
  arc A4 centre (183.6727, -52.1463) radius 1 clockwise from (182.6759, -52.2261) to (183.5626, -51.1524)
  arc A5 centre (180, -19) radius 32.3492 clockwise from (184.8805, -50.9789) to (183.5626, -51.1524)
  arc A6 centre (185.0314, -51.9675) radius 1 clockwise from (184.8805, -50.9789) to (186.0148, -51.7865)
  arc A7 centre (180, -19) radius 39 clockwise from (191.1267, -56.3791) to (189.0535, -56.9346)
  arc A8 centre (192.1265, -50.0663) radius 1 clockwise from (191.1842, -50.4014) to (191.7628, -49.1348)
  arc A9 centre (180, -19) radius 32.3492 clockwise from (192.9909, -48.6261) to (191.7628, -49.1348)
  arc A10 centre (193.3925, -49.5419) radius 1 clockwise from (192.9909, -48.6261) to (194.2957, -49.1126)
  arc A11 centre (180, -19) radius 39 clockwise from (200.422, -52.2256) to (198.5632, -53.2988)
  arc A12 centre (199.7538, -45.8692) radius 1 clockwise from (198.9304, -46.4367) to (199.1615, -45.0635)
  arc A13 centre (180, -19) radius 32.3492 clockwise from (200.2161, -44.2543) to (199.1615, -45.0635)
  arc A14 centre (200.841, -45.035) radius 1 clockwise from (200.2161, -44.2543) to (201.6023, -44.3865)
  arc A15 centre (180, -19) radius 39 clockwise from (208.3256, -45.8079) to (206.8079, -47.3256)
  arc A16 centre (206.035, -39.841) radius 1 clockwise from (205.3865, -40.6023) to (205.2543, -39.2161)
  arc A17 centre (180, -19) radius 32.3492 clockwise from (206.0635, -38.1615) to (205.2543, -39.2161)
  arc A18 centre (206.8692, -38.7538) radius 1 clockwise from (206.0635, -38.1615) to (207.4367, -37.9304)
  arc A19 centre (180, -19) radius 39 clockwise from (214.2988, -37.5632) to (213.2256, -39.422)
  arc A20 centre (210.5419, -32.3925) radius 1 clockwise from (210.1126, -33.2957) to (209.6261, -31.9909)
  arc A21 centre (180, -19) radius 32.3492 clockwise from (210.1348, -30.7628) to (209.6261, -31.9909)
  arc A22 centre (211.0663, -31.1265) radius 1 clockwise from (210.1348, -30.7628) to (211.4014, -30.1842)
  arc A23 centre (180, -19) radius 39 clockwise from (217.9346, -28.0535) to (217.3791, -30.1267)
  arc A24 centre (212.9675, -24.0314) radius 1 clockwise from (212.7865, -25.0148) to (211.9789, -23.8805)
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extrude "Extrude3" new body sketch "Sketch6" along normal blind 3
move "Move2"
offset_faces "OffsetFaces1" distance -2
move "Move3"
move "Move4"
move "Move5" TranslateX 3 TranslateY 0 TranslateZ 0
move "Move6" TranslateX -7 TranslateY 0 TranslateZ 0
sketch "Sketch7" plane through (13.9981, 0, 0) normal (1, 0, 0) x axis (0, 1, 0)
  line L1 (182.8553, -51.9321) -> (182.8948, -51.4384)
  curve K1 (184.4974, -57.1975) -> (182.8553, -51.9321)
  curve K2 (188.286, -51.9321) -> (186.6438, -57.1975)
  line L2 (188.2465, -51.4384) -> (188.286, -51.9321)
  line L3 (191.6751, -51.4859) -> (191.5855, -50.9988)
  curve K3 (194.6241, -56.1469) -> (191.6751, -51.4859)
  curve K4 (196.9208, -50.0803) -> (196.6974, -55.5914)
  line L4 (196.7549, -49.6136) -> (196.9208, -50.0803)
  line L5 (200.0789, -48.7722) -> (199.8663, -48.3249)
  curve K5 (204.1338, -52.5111) -> (200.0789, -48.7722)
  curve K6 (204.7821, -46.0568) -> (205.9927, -51.4379)
  line L6 (204.5011, -45.649) -> (204.7821, -46.0568)
  line L7 (207.4941, -43.9758) -> (207.1729, -43.5988)
  curve K7 (212.3785, -46.5379) -> (207.4941, -43.9758)
  curve K8 (211.3342, -40.1357) -> (213.8962, -45.0201)
  line L8 (210.9572, -39.8145) -> (211.3342, -40.1357)
  line L9 (213.4151, -37.4238) -> (213.0073, -37.1427)
  curve K9 (218.7962, -38.6343) -> (213.4151, -37.4238)
  curve K10 (216.1305, -32.7206) -> (219.8694, -36.7755)
  line L10 (215.6832, -32.5079) -> (216.1305, -32.7206)
  line L11 (217.4387, -29.5625) -> (216.972, -29.3965)
  curve K11 (222.9497, -29.339) -> (217.4387, -29.5625)
  curve K12 (218.8442, -24.3168) -> (223.5052, -27.2658)
  line L12 (218.3571, -24.2271) -> (218.8442, -24.3168)
  line L13 (219.2904, -20.9277) -> (218.7967, -20.8882)
  curve K13 (224.5559, -19.2855) -> (219.2904, -20.9277)
  curve K14 (219.2904, -15.4969) -> (224.5559, -17.1391)
  line L14 (218.7967, -15.5364) -> (219.2904, -15.4969)
  line L15 (218.8442, -12.1078) -> (218.3571, -12.1974)
  curve K15 (223.5052, -9.1588) -> (218.8442, -12.1078)
  curve K16 (217.4387, -6.8621) -> (222.9497, -7.0855)
  line L16 (216.972, -7.028) -> (217.4387, -6.8621)
  line L17 (216.1305, -3.704) -> (215.6832, -3.9166)
  curve K17 (219.8694, 0.3509) -> (216.1305, -3.704)
  curve K18 (213.4151, 0.9992) -> (218.7962, 2.2097)
  line L18 (213.0073, 0.7181) -> (213.4151, 0.9992)
  line L19 (211.3342, 3.7111) -> (210.9572, 3.39)
  curve K19 (213.8962, 8.5956) -> (211.3342, 3.7111)
  curve K20 (207.4941, 7.5513) -> (212.3785, 10.1133)
  line L20 (207.1729, 7.1742) -> (207.4941, 7.5513)
  line L21 (204.7821, 9.6322) -> (204.5011, 9.2244)
  curve K21 (205.9927, 15.0133) -> (204.7821, 9.6322)
  curve K22 (200.0789, 12.3476) -> (204.1338, 16.0865)
  line L22 (199.8663, 11.9003) -> (200.0789, 12.3476)
  line L23 (196.9208, 13.6557) -> (196.7549, 13.1891)
  curve K23 (196.6974, 19.1668) -> (196.9208, 13.6557)
  curve K24 (191.6751, 15.0613) -> (194.6241, 19.7223)
  line L24 (191.5855, 14.5742) -> (191.6751, 15.0613)
  line L25 (188.286, 15.5075) -> (188.2465, 15.0138)
  curve K25 (186.6438, 20.7729) -> (188.286, 15.5075)
  curve K26 (182.8553, 15.5075) -> (184.4974, 20.7729)
  line L26 (182.8948, 15.0138) -> (182.8553, 15.5075)
  line L27 (179.4662, 15.0613) -> (179.5558, 14.5742)
  curve K27 (176.5171, 19.7223) -> (179.4662, 15.0613)
  curve K28 (174.2205, 13.6557) -> (174.4439, 19.1668)
  line L28 (174.3864, 13.1891) -> (174.2205, 13.6557)
  line L29 (171.0623, 12.3476) -> (171.275, 11.9003)
  curve K29 (167.0074, 16.0865) -> (171.0623, 12.3476)
  curve K30 (166.3592, 9.6322) -> (165.1486, 15.0133)
  line L30 (166.6402, 9.2244) -> (166.3592, 9.6322)
  line L31 (163.6472, 7.5513) -> (163.9684, 7.1742)
  curve K31 (158.7628, 10.1133) -> (163.6472, 7.5513)
  curve K32 (159.8071, 3.7111) -> (157.2451, 8.5956)
  line L32 (160.1841, 3.39) -> (159.8071, 3.7111)
  line L33 (157.7261, 0.9992) -> (158.1339, 0.7181)
  curve K33 (152.345, 2.2097) -> (157.7261, 0.9992)
  curve K34 (155.0108, -3.704) -> (151.2718, 0.3509)
  line L34 (155.4581, -3.9166) -> (155.0108, -3.704)
  line L35 (153.7026, -6.8621) -> (154.1693, -7.028)
  curve K35 (148.1916, -7.0855) -> (153.7026, -6.8621)
  curve K36 (152.297, -12.1078) -> (147.636, -9.1588)
  line L36 (152.7841, -12.1974) -> (152.297, -12.1078)
  line L37 (151.8509, -15.4969) -> (152.3446, -15.5364)
  curve K37 (146.5854, -17.1391) -> (151.8509, -15.4969)
  curve K38 (151.8509, -20.9277) -> (146.5854, -19.2855)
  line L38 (152.3446, -20.8882) -> (151.8509, -20.9277)
  line L39 (152.297, -24.3168) -> (152.7841, -24.2271)
  curve K39 (147.636, -27.2658) -> (152.297, -24.3168)
  curve K40 (153.7026, -29.5625) -> (148.1916, -29.339)
  line L40 (154.1693, -29.3965) -> (153.7026, -29.5625)
  line L41 (155.0108, -32.7206) -> (155.4581, -32.5079)
  curve K41 (151.2718, -36.7755) -> (155.0108, -32.7206)
  curve K42 (157.7261, -37.4238) -> (152.345, -38.6343)
  line L42 (158.1339, -37.1427) -> (157.7261, -37.4238)
  line L43 (159.8071, -40.1357) -> (160.1841, -39.8145)
  curve K43 (157.2451, -45.0201) -> (159.8071, -40.1357)
  curve K44 (163.6472, -43.9758) -> (158.7628, -46.5379)
  line L44 (163.9684, -43.5988) -> (163.6472, -43.9758)
  line L45 (166.3592, -46.0568) -> (166.6402, -45.649)
  curve K45 (165.1486, -51.4379) -> (166.3592, -46.0568)
  curve K46 (171.0623, -48.7722) -> (167.0074, -52.5111)
  line L46 (171.275, -48.3249) -> (171.0623, -48.7722)
  line L47 (174.2205, -50.0803) -> (174.3864, -49.6136)
  curve K47 (174.4439, -55.5914) -> (174.2205, -50.0803)
  curve K48 (179.4662, -51.4859) -> (176.5171, -56.1469)
  line L48 (179.5558, -50.9988) -> (179.4662, -51.4859)
  line L49 (189.7947, -21.9467) -> (189.6413, -21.8116)
  curve K49 (190.953, -22.2857) -> (189.7947, -21.9467)
  curve K50 (190.5246, -20.9044) -> (191.2393, -21.8768)
  line L50 (190.3451, -20.8065) -> (190.5246, -20.9044)
  line L51 (190.9023, -20.0459) -> (190.7088, -19.9798)
  curve K51 (192.1021, -19.9159) -> (190.9023, -20.0459)
  curve K52 (191.1777, -18.8037) -> (192.2101, -19.4286)
  line L52 (190.9744, -18.7819) -> (191.1777, -18.8037)
  line L53 (191.1981, -17.866) -> (190.9941, -17.879)
  curve K53 (192.2569, -17.2868) -> (191.1981, -17.866)
  curve K54 (190.9772, -16.6129) -> (192.1702, -16.7952)
  line L54 (190.7811, -16.6706) -> (190.9772, -16.6129)
  line L55 (190.6373, -15.7388) -> (190.4537, -15.8288)
  curve K55 (191.3937, -14.7985) -> (190.6373, -15.7388)
  curve K56 (189.9536, -14.6657) -> (191.1255, -14.3775)
  line L56 (189.7944, -14.794) -> (189.9536, -14.6657)
  line L57 (189.305, -13.9882) -> (189.1699, -14.1416)
  curve K57 (189.6441, -12.8299) -> (189.305, -13.9882)
  curve K58 (188.2628, -13.2584) -> (189.2352, -12.5436)
  line L58 (188.1648, -13.4378) -> (188.2628, -13.2584)
  line L59 (187.4043, -12.8806) -> (187.3382, -13.0741)
  curve K59 (187.2743, -11.6808) -> (187.4043, -12.8806)
  curve K60 (186.162, -12.6052) -> (186.7869, -11.5728)
  line L60 (186.1402, -12.8085) -> (186.162, -12.6052)
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extrude "Extrude4" new body sketch "Sketch7" along normal blind 4
combine "Combine2"
sketch "Sketch8" plane through (18.9981, 0, 0) normal (1, 0, 0) x axis (0, 1, 0)
  line L1 (149.9264, -64.082) -> (149.9977, -63.8919)
  line L2 (132.0175, -155.1313) -> (149.9264, -64.082)
  line L3 (171.9916, -32.8813) -> (200.2987, -133.9094)
  line L4 (149.9977, -63.8919) -> (155.6873, -48.7302)
  arc A1 centre (162.3398, -25.3102) radius 133.3153 clockwise from (186.1858, -156.4755) to (132.0175, -155.1313)
  arc A2 centre (182.9662, -138.7658) radius 18 clockwise from (200.2987, -133.9094) to (186.1858, -156.4755)
  arc A3 centre (162.3398, -25.3102) radius 12.267 clockwise from (152.9897, -33.2509) to (171.9916, -32.8813)
  arc A4 centre (141.1755, -43.2845) radius 15.5 clockwise from (152.9897, -33.2509) to (155.6873, -48.7302)
  circle C1 centre (162.4377, -25.1855) radius 3.5
  circle C2 centre (185.5706, -18.2123) radius 2.5
extrude "Extrude5" new body sketch "Sketch8" profile of C1 C2 along normal blind 1 and against normal blind 8
sketch "Sketch9" plane through (19.9981, 0, 0) normal (1, 0, 0) x axis (0, 1, 0)
  line L1 (233.7172, -15.2961) -> (144.3129, -15.2961)
  line L2 (233.7172, -29.6952) -> (233.7172, -15.2961)
  line L3 (144.3129, -29.6952) -> (233.7172, -29.6952)
  line L4 (144.3129, -15.2961) -> (144.3129, -29.6952)
  circle C1 centre (162.4377, -25.1855) radius 3.5
  horizontal L1
  vertical L2
  horizontal L3
  vertical L4
extrude "Extrude6" new body sketch "Sketch9" along normal blind 2
copy_paste_bodies "CopyPasteBodies1"
split "Split3"
delete_face "DeleteFace4"
copy_paste_bodies "CopyPasteBodies2"
move "Move7" RotateAngle 30
split "Split4"
move "Move8" TranslateX -1 TranslateY 0 TranslateZ 0
move "Move9" TranslateX 1 TranslateY 0 TranslateZ 0
move "Move10" TranslateX -1 TranslateY 0 TranslateZ 0
move "Move11" TranslateX 1 TranslateY 0 TranslateZ 0
combine "Combine3"
combine "Combine4"
move "Move12" TranslateX -1.2 TranslateY 0 TranslateZ 0
combine "Combine5"
sketch "Sketch10" plane through (12.4927, 0, 0) normal (1, 0, 0) x axis (0, 1, 0)
  line L1 (199.7459, -62.1263) -> (199.7359, -62.129)
  line L2 (219.2287, -134.5488) -> (199.7459, -62.1263)
  line L3 (236.0655, -130.0194) -> (219.2287, -134.5488)
  line L4 (216.582, -57.5943) -> (236.0655, -130.0194)
  line L5 (199.7352, -62.1263) -> (216.582, -57.5943)
  line L6 (199.7359, -62.129) -> (199.7352, -62.1263)
  line L7 (180.4535, -30.0794) -> (250.9108, -98.9502)
  line L8 (264.2845, -109.7593) -> (183.9989, -31.2814)
  line L9 (233.7172, -29.6952) -> (144.3129, -29.6952)
  line L10 (182.3761, -29.6952) -> (183.9989, -31.2814)
  line L11 (233.7172, -79.8803) -> (233.7172, -29.6952)
  line L12 (233.7172, -15.2961) -> (144.3129, -15.2961)
  line L13 (196.2783, -29.6952) -> (233.7172, -29.6952)
  line L14 (196.2783, -15.2961) -> (196.2783, -29.6952)
  line L15 (233.7172, -15.2961) -> (196.2783, -15.2961)
  line L16 (233.7172, -29.6952) -> (233.7172, -15.2961)
  point P14 (182.3761, -29.6952)
  point P13 (233.7172, -29.6952)
  point P15 (233.7172, -29.6952)
  point P16 (233.7172, -79.8803)
  point P20 (196.2783, -15.2961)
  parallel L7 L8
  coincident L9 P14
  parallel L8 L10
  coincident P13 P15
  coincident L8 P16
  perpendicular L9 L11
  horizontal L13
  vertical L14
  horizontal L15
  vertical L16
  coincident L12 P20
extrude "Extrude7" new body sketch "Sketch10" profile of L4 L5 L8 L9 L10 L11 L12 L13 L14 L15 L16 along normal blind 7.505
sketch "Sketch11" plane through (0, 233.7172, 0) normal (0, 1, 0) x axis (-1, 0, 0)
  line L1 (-12.4927, -15.2961) -> (-12.4927, -79.8803)
  line L2 (-19.9977, -15.2961) -> (-12.4927, -15.2961)
  line L3 (-19.9977, -79.8803) -> (-19.9977, -15.2961)
  line L4 (-12.4927, -79.8803) -> (-19.9977, -79.8803)
  line L5 (-15, -15.2961) -> (-12.4927, -15.2961)
  line L6 (-15, -58) -> (-15, -15.2961)
  line L7 (-12.4927, -58) -> (-15, -58)
  line L8 (-12.4927, -15.2961) -> (-12.4927, -58)
  point P3 (-12.4927, -15.2961)
  point P6 (-12.4927, -15.2961)
  horizontal L5
  vertical L6
  horizontal L7
  vertical L8
  coincident P3 P6
split "Split5"
move_face "MoveFace3" TranslateX -2 TranslateY 0 TranslateZ 0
